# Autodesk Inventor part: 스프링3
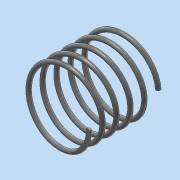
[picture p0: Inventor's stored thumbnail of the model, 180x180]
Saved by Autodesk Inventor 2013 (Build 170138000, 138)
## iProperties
Created: 2015-11
Part Number: 스프링3
Material: 강철, 탄소
Document SubType Name: Modeling
Designer: dgall
Density: 7.87 g/cm^3
Mass: 1.54359 g
Surface Area: 7.88921 cm^2
Volume: 0.196136 cm^3
Author: dgall
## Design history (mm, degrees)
sketch "스케치1"
  geometry: L1 (0, 0)-(8, 0); L2 (0, 0)-(0, 16.67); L3 (0, 16.67)-(8, 16.67); C1 r 0.5 at (8, 0)
  constraints: 6 end point, 2 perpendicular, 1 centre point, 1 coincident, 1 horizontal, 1 vertical alignment
  dimensions: "d0" = 16 diameter of L1.end L2; "d2" = 16.66987 distance of L1.start L2.end (derived); "d3" = 1 diameter of C1
feature "코일1" sketch "스케치1" pitch "d4" = 10; turns "d6" = 5; dims "d5" = 16.66987 (= d2), "d7" = 0, angle "d8" = 90 deg, angle "d9" = 90 deg, "d10" = 0, "d11" = 0
node "작업 평면1"
feature "분할1"
feature "분할2"
node "솔리드1"
other parameters: "d12" = 25
